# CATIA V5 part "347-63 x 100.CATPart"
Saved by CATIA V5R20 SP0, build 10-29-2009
Part number: 347-63 x 100
Definition: NONE
Nomenclature: 347-63 x 100
Source: Unknown
Description: 347-63 x 100
Bounding box of the stored display mesh (mm): x 0 to 100, y -42.5 to 42.5, z -42.5 to 42.5
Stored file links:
  C:\Users\Utente\Desktop\IO LAVORO\3D X SITO CF\X SITO\3D files 347\347-63 x 100.CATPart
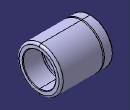
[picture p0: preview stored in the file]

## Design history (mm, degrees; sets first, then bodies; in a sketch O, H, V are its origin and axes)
Body1 "347-63 x 100" (main body)
  Solid1: solid without history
